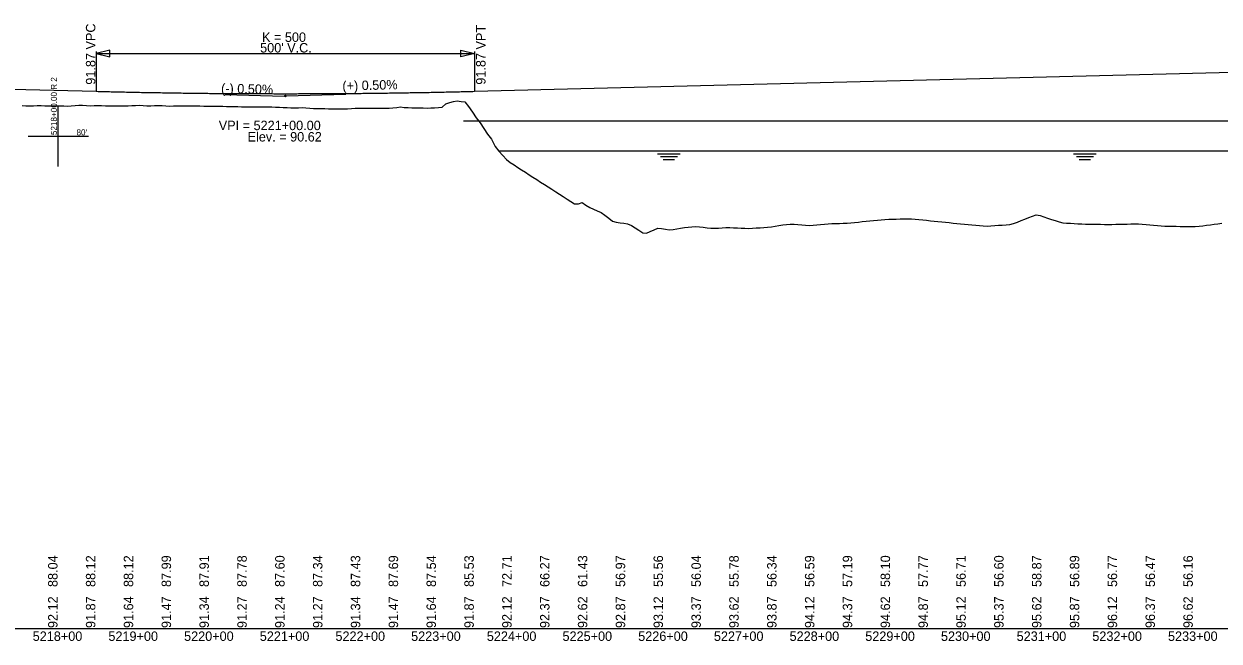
# Model space of a CAD drawing. Extents: x 2147288 to 2220488, y 740833 to 759333.
# Drawn here: x 2154136 to 2155715, y 750067 to 750882 of the extents above; entities that cross this region are included whole.
import ezdxf

# ---------------------------------------------------------------- set-up
doc = ezdxf.new("R2010")
doc.units = 0
for name, color, linetype in [('RD_DDB_GradeTX', 7, 'Continuous'), ('RD_DDB_Profile_Elev', 7, 'Continuous'), ('RD_DDB_Profile_EX', 7, 'Continuous'), ('RD_DDB_Profile_Lbl', 7, 'Continuous'), ('RD_DDB_Profile_PR', 7, 'Continuous'), ('RD_DDB_StaTX', 7, 'Continuous'), ('RD_DDB_StripGrade', 7, 'Continuous'), ('RD_DDB_VCLbl', 7, 'Continuous'), ('RD_GPK_Profile_Cell', 7, 'Continuous')]:
    doc.layers.add(name, color=color, linetype=linetype)

msp = doc.modelspace()

# ---------------------------------------------------------------- linework, layer by layer
at = {"layer": 'RD_DDB_GradeTX'}
for p, q in [((2154401.1, 750788.5), (2154480.1, 750786.5)), ((2154561.1, 750788.5), (2154482.1, 750786.5))]:
    msp.add_line(p, q, dxfattribs=at)
msp.add_circle((2154481.1, 750786.5), 1, dxfattribs=at)
at = {"layer": 'RD_DDB_Profile_Elev'}
for p, q in [((2154716.7, 750754), (2158451.2, 750754)), ((2154763.1, 750714), (2159128.1, 750714)), ((2154972.8, 750710.3), (2155002.8, 750710.3)), ((2154976.6, 750706.5), (2154999.1, 750706.5)), ((2155522.4, 750710.3), (2155552.4, 750710.3)), ((2155526.2, 750706.5), (2155548.7, 750706.5)), ((2154980.3, 750702.8), (2154995.3, 750702.8)), ((2155529.9, 750702.8), (2155544.9, 750702.8))]:
    msp.add_line(p, q, dxfattribs=at)
at = {"layer": 'RD_DDB_Profile_EX'}
for points in [[(2154133.3, 750773.9), (2154138.3, 750773.7), (2154143.3, 750773.6), (2154148.3, 750773.7), (2154153.3, 750774), (2154158.3, 750773.9), (2154163.3, 750773.7), (2154168.3, 750773.4), (2154173.3, 750773.4), (2154178.3, 750773.6), (2154183.3, 750773.7), (2154188.3, 750773.7), (2154193.3, 750773.3), (2154198.3, 750773.6), (2154203.3, 750774.1), (2154208.3, 750774.4), (2154213.3, 750774.6), (2154218.3, 750774), (2154223.3, 750773.5), (2154228.3, 750773.9), (2154233.3, 750774.1), (2154238.3, 750773.9), (2154243.3, 750773.8), (2154248.3, 750773.8), (2154253.3, 750773.7), (2154258.3, 750773.7), (2154263.3, 750773.7), (2154268.3, 750773.8), (2154273.3, 750773.8), (2154278.3, 750774), (2154283.3, 750774.1), (2154288.3, 750774.3), (2154293.3, 750774.2), (2154298.3, 750773.7), (2154303.3, 750773.7), (2154308.3, 750773.9), (2154313.3, 750774), (2154318.3, 750774), (2154323.3, 750773.5), (2154328.3, 750773.2), (2154333.3, 750773.6), (2154338.3, 750773.7), (2154343.3, 750773.5), (2154348.3, 750773.4), (2154353.3, 750773.5), (2154358.3, 750773.5), (2154363.3, 750773.5), (2154368.3, 750773.5), (2154373.3, 750773.2), (2154378.3, 750773), (2154383.3, 750773), (2154388.3, 750773), (2154393.3, 750773.1), (2154398.3, 750773), (2154403.3, 750772.9), (2154408.3, 750772.9), (2154413.3, 750772.9), (2154418.3, 750772.8), (2154423.3, 750772.5), (2154428.3, 750772.3), (2154433.3, 750772.3), (2154438.3, 750772.2), (2154443.3, 750772.4), (2154448.3, 750772.5), (2154453.3, 750772.5), (2154458.3, 750772.4), (2154463.3, 750772.2), (2154468.3, 750772), (2154473.3, 750771.7), (2154478.3, 750771.5), (2154483.3, 750771.3), (2154488.3, 750771.1), (2154493.3, 750770.9), (2154498.3, 750771.1), (2154503.3, 750771.3), (2154508.3, 750770.9), (2154513.3, 750770.5), (2154518.3, 750770.2), (2154523.3, 750770.1), (2154528.3, 750770.3), (2154533.3, 750770), (2154538.3, 750769.8)], [(2154538.3, 750769.8), (2154543.3, 750769.8), (2154548.3, 750769.7), (2154553.3, 750769.8), (2154558.3, 750769.7), (2154563.3, 750769.6), (2154568.3, 750770.1), (2154573.3, 750770.5), (2154578.3, 750770.5), (2154583.3, 750770.6), (2154588.3, 750770.6), (2154593.3, 750770.6), (2154598.3, 750770.5), (2154603.3, 750770.4), (2154608.3, 750770.4), (2154613.3, 750770.5), (2154618.3, 750770.7), (2154623.3, 750770.9), (2154628.3, 750771.6), (2154633.3, 750772.1), (2154638.3, 750771.3), (2154643.3, 750771.2), (2154648.3, 750771.1), (2154653.3, 750770.8), (2154658.3, 750771), (2154663.3, 750770.8), (2154668.3, 750770.6), (2154673.3, 750770.8), (2154678.3, 750770.8), (2154683.3, 750771.4), (2154688.3, 750772), (2154693.3, 750776.1), (2154698.3, 750777.8), (2154703.3, 750779.5), (2154708.3, 750780.2), (2154713.3, 750779.5), (2154718.3, 750778.7), (2154723.3, 750772.6), (2154728.3, 750765.1), (2154733.3, 750757.9), (2154738.3, 750751.2), (2154743.3, 750743.8), (2154748.3, 750736.1), (2154753.3, 750729.5), (2154758.3, 750720.1), (2154763.3, 750713.8), (2154768.3, 750708.2), (2154773.3, 750702.8), (2154778.3, 750698.8), (2154783.3, 750695.5), (2154788.3, 750692.3), (2154793.3, 750689.1), (2154798.3, 750685.9), (2154803.3, 750682.7), (2154808.3, 750679.5), (2154813.3, 750676.2), (2154818.3, 750673), (2154823.3, 750669.8), (2154828.3, 750666.6), (2154833.3, 750663.4), (2154838.3, 750660.2), (2154843.3, 750657), (2154848.3, 750653.7), (2154853.3, 750650.5), (2154858.3, 750647.3), (2154863.3, 750644.4), (2154868.3, 750644.1), (2154873.3, 750645.8), (2154878.3, 750642.4), (2154883.3, 750639.2), (2154888.3, 750637.1), (2154893.3, 750635), (2154898.3, 750632.9), (2154903.3, 750629.1), (2154908.3, 750625.2), (2154913.3, 750621.3), (2154918.3, 750620), (2154923.3, 750619.3), (2154928.3, 750618.6), (2154933.3, 750618), (2154938.3, 750615.8), (2154943.3, 750612.6), (2154948.3, 750609.3), (2154953.3, 750606.1), (2154958.3, 750605.3), (2154963.3, 750607.5), (2154968.3, 750609.7), (2154973.3, 750612), (2154978.3, 750611.7), (2154983.3, 750610.9), (2154988.3, 750610.1), (2154993.3, 750610.4), (2154998.3, 750611.3), (2155003.3, 750612.1), (2155008.3, 750612.9), (2155013.3, 750613.4), (2155018.3, 750614), (2155023.3, 750614.5), (2155028.3, 750614), (2155033.3, 750613.3), (2155038.3, 750612.6)], [(2155038.3, 750612.6), (2155043.3, 750611.9), (2155048.3, 750612), (2155053.3, 750612.3), (2155058.3, 750612.5), (2155063.3, 750612.8), (2155068.3, 750613), (2155073.3, 750612.7), (2155078.3, 750612.4), (2155083.3, 750612.2), (2155088.3, 750612), (2155093.3, 750611.8), (2155098.3, 750612), (2155103.3, 750612.4), (2155108.3, 750612.7), (2155113.3, 750613.1), (2155118.3, 750613.5), (2155123.3, 750613.9), (2155128.3, 750614.7), (2155133.3, 750615.5), (2155138.3, 750616.3), (2155143.3, 750617.1), (2155148.3, 750617.6), (2155153.3, 750617.2), (2155158.3, 750616.8), (2155163.3, 750616.4), (2155168.3, 750616), (2155173.3, 750615.6), (2155178.3, 750616.1), (2155183.3, 750616.6), (2155188.3, 750617), (2155193.3, 750617.5), (2155198.3, 750618), (2155203.3, 750618.4), (2155208.3, 750618.1), (2155213.3, 750618.4), (2155218.3, 750618.6), (2155223.3, 750618.9), (2155228.3, 750619.2), (2155233.3, 750619.5), (2155238.3, 750620.2), (2155243.3, 750620.7), (2155248.3, 750621.2), (2155253.3, 750621.7), (2155258.3, 750622.2), (2155263.3, 750622.6), (2155268.3, 750623.1), (2155273.3, 750623.7), (2155278.3, 750623.9), (2155283.3, 750624), (2155288.3, 750624.2), (2155293.3, 750624.3), (2155298.3, 750624.4), (2155303.3, 750624.6), (2155308.3, 750624.6), (2155313.3, 750624.1), (2155318.3, 750623.6), (2155323.3, 750623.1), (2155328.3, 750622.6), (2155333.3, 750622), (2155338.3, 750621.5), (2155343.3, 750620.9), (2155348.3, 750620.4), (2155353.3, 750619.9), (2155358.3, 750619.4), (2155363.3, 750618.9), (2155368.3, 750618.4), (2155373.3, 750617.7), (2155378.3, 750617.2), (2155383.3, 750616.8), (2155388.3, 750616.4), (2155393.3, 750616), (2155398.3, 750615.6), (2155403.3, 750615.2), (2155408.3, 750614.8), (2155413.3, 750615.2), (2155418.3, 750615.5), (2155423.3, 750615.9), (2155428.3, 750616.2), (2155433.3, 750616.6), (2155438.3, 750616.9), (2155443.3, 750618.3), (2155448.3, 750620.2), (2155453.3, 750622.2), (2155458.3, 750624.1), (2155463.3, 750626.1), (2155468.3, 750628), (2155473.3, 750629.8), (2155478.3, 750628.7), (2155483.3, 750627), (2155488.3, 750625.4), (2155493.3, 750623.7), (2155498.3, 750622.1), (2155503.3, 750620.4), (2155508.3, 750619.2), (2155513.3, 750618.8), (2155518.3, 750618.5), (2155523.3, 750618.3), (2155528.3, 750618), (2155533.3, 750617.7), (2155538.3, 750617.5)], [(2155538.3, 750617.5), (2155543.3, 750617.3), (2155548.3, 750617.3), (2155553.3, 750617.3), (2155558.3, 750617.2), (2155563.3, 750617.1), (2155568.3, 750617), (2155573.3, 750617), (2155578.3, 750617.2), (2155583.3, 750617.3), (2155588.3, 750617.5), (2155593.3, 750617.6), (2155598.3, 750617.7), (2155603.3, 750617.9), (2155608.3, 750618), (2155613.3, 750617.4), (2155618.3, 750617), (2155623.3, 750616.5), (2155628.3, 750616), (2155633.3, 750615.6), (2155638.3, 750615.1), (2155643.3, 750614.7), (2155648.3, 750614.7), (2155653.3, 750614.6), (2155658.3, 750614.6), (2155663.3, 750614.5), (2155668.3, 750614.4), (2155673.3, 750614.3), (2155678.3, 750614.2), (2155683.3, 750614.3), (2155688.3, 750614.8), (2155693.3, 750615.4), (2155698.3, 750616), (2155703.3, 750616.6), (2155708.3, 750617.2), (2155713.3, 750617.7), (2155718.3, 750618.5)]]:
    msp.add_lwpolyline(points, dxfattribs=at)
at = {"layer": 'RD_DDB_Profile_PR'}
for p, q in [((2154731.1, 750792.8), (2156331.1, 750832.8)), ((2154031.1, 750797.8), (2154231.1, 750792.8))]:
    msp.add_line(p, q, dxfattribs=at)
msp.add_spline([(2154231.1, 750792.8), (2154241.1, 750792.5), (2154251.1, 750792.3), (2154261.1, 750792.1), (2154271.1, 750791.8), (2154281.1, 750791.6), (2154291.1, 750791.4), (2154301.1, 750791.3), (2154311.1, 750791.1), (2154321.1, 750790.9), (2154331.1, 750790.8), (2154341.1, 750790.6), (2154351.1, 750790.5), (2154361.1, 750790.4), (2154371.1, 750790.2), (2154381.1, 750790.1), (2154391.1, 750790), (2154401.1, 750790), (2154411.1, 750789.9), (2154421.1, 750789.8), (2154431.1, 750789.8), (2154441.1, 750789.7), (2154451.1, 750789.7), (2154461.1, 750789.7), (2154471.1, 750789.6), (2154481.1, 750789.6), (2154491.1, 750789.6), (2154501.1, 750789.7), (2154511.1, 750789.7), (2154521.1, 750789.7), (2154531.1, 750789.8), (2154541.1, 750789.8), (2154551.1, 750789.9), (2154561.1, 750790), (2154571.1, 750790), (2154581.1, 750790.1), (2154591.1, 750790.2), (2154601.1, 750790.4), (2154611.1, 750790.5), (2154621.1, 750790.6), (2154631.1, 750790.8), (2154641.1, 750790.9), (2154651.1, 750791.1), (2154661.1, 750791.3), (2154671.1, 750791.4), (2154681.1, 750791.6), (2154691.1, 750791.8), (2154701.1, 750792.1), (2154711.1, 750792.3), (2154721.1, 750792.5), (2154731.1, 750792.8)], degree=3, dxfattribs=at)
at = {"layer": 'RD_DDB_VCLbl'}
for p, q in [((2154231.1, 750845.3), (2154231.1, 750792.8)), ((2154231.1, 750842.8), (2154731.1, 750842.8)), ((2154731.1, 750845.3), (2154731.1, 750792.8))]:
    msp.add_line(p, q, dxfattribs=at)
for points in [[(2154249.1, 750847.3), (2154231.1, 750842.8), (2154249.1, 750838.3)], [(2154713.1, 750847.3), (2154731.1, 750842.8), (2154713.1, 750838.3)]]:
    msp.add_lwpolyline(points, close=True, dxfattribs=at)
at = {"layer": 'RD_GPK_Profile_Cell'}
for p, q in [((2154181.1, 750693.4), (2154181.1, 750773.4)), ((2154141.1, 750733.4), (2154221.1, 750733.4)), ((2148888.3, 750083.4), (2170488.3, 750083.4))]:
    msp.add_line(p, q, dxfattribs=at)

# ---------------------------------------------------------------- texts
at = {"layer": 'RD_DDB_GradeTX'}
for s, rotation, p in [('(-) 0.50%', 358.5679, (2154396.1, 750790.6)), ('(+) 0.50%', 1.4321, (2154556.6, 750793.7))]:
    msp.add_text(s, height=12.5, rotation=rotation, dxfattribs=at).set_placement(p)
at = {"layer": 'RD_DDB_Profile_Lbl'}
for s, p in [('VPI = 5221+00.00', (2154393.1, 750741.5)), ('Elev. = 90.62', (2154431.2, 750726.5))]:
    msp.add_text(s, height=12.5, dxfattribs=at).set_placement(p)
at = {"layer": 'RD_DDB_StaTX'}
for s, p in [('5218+00', (2154147.3, 750067.2)), ('5219+00', (2154247.3, 750067.2)), ('5220+00', (2154347.3, 750067.2)), ('5221+00', (2154447.3, 750067.2)), ('5222+00', (2154547.3, 750067.2)), ('5223+00', (2154647.3, 750067.2)), ('5224+00', (2154747.3, 750067.2)), ('5225+00', (2154847.3, 750067.2)), ('5226+00', (2154947.3, 750067.2)), ('5227+00', (2155047.3, 750067.2)), ('5228+00', (2155147.3, 750067.2)), ('5229+00', (2155247.3, 750067.2)), ('5230+00', (2155347.3, 750067.2)), ('5231+00', (2155447.3, 750067.2)), ('5232+00', (2155547.3, 750067.2)), ('5233+00', (2155647.3, 750067.2))]:
    msp.add_text(s, height=12.5, dxfattribs=at).set_placement(p)
at = {"layer": 'RD_DDB_StripGrade'}
for s, p in [('91.87 VPC', (2154230.1, 750801.5)), ('91.87 VPT', (2154745.6, 750801.5)), ('88.04', (2154180.1, 750138.4)), ('88.12', (2154230.1, 750138.4)), ('88.12', (2154280.1, 750138.4)), ('87.99', (2154330.1, 750138.4)), ('87.91', (2154380.1, 750138.4)), ('87.78', (2154430.1, 750138.4)), ('87.60', (2154480.1, 750138.4)), ('87.34', (2154530.1, 750138.4)), ('87.43', (2154580.1, 750138.4)), ('87.69', (2154630.1, 750138.4)), ('87.54', (2154680.1, 750138.4)), ('85.53', (2154730.1, 750138.4)), ('72.71', (2154780.1, 750138.4)), ('66.27', (2154830.1, 750138.4)), ('61.43', (2154880.1, 750138.4)), ('56.97', (2154930.1, 750138.4)), ('55.56', (2154980.1, 750138.4)), ('56.04', (2155030.1, 750138.4)), ('55.78', (2155080.1, 750138.4)), ('56.34', (2155130.1, 750138.4)), ('56.59', (2155180.1, 750138.4)), ('57.19', (2155230.1, 750138.4)), ('58.10', (2155280.1, 750138.4)), ('57.77', (2155330.1, 750138.4)), ('56.71', (2155380.1, 750138.4)), ('56.60', (2155430.1, 750138.4)), ('58.87', (2155480.1, 750138.4)), ('56.89', (2155530.1, 750138.4)), ('56.77', (2155580.1, 750138.4)), ('56.47', (2155630.1, 750138.4)), ('56.16', (2155680.1, 750138.4)), ('92.12', (2154180.1, 750084.2)), ('91.87', (2154230.1, 750084.2)), ('91.64', (2154280.1, 750084.2)), ('91.47', (2154330.1, 750084.2)), ('91.34', (2154380.1, 750084.2)), ('91.27', (2154430.1, 750084.2)), ('91.24', (2154480.1, 750084.2)), ('91.27', (2154530.1, 750084.2)), ('91.34', (2154580.1, 750084.2)), ('91.47', (2154630.1, 750084.2)), ('91.64', (2154680.1, 750084.2)), ('91.87', (2154730.1, 750084.2)), ('92.12', (2154780.1, 750084.2)), ('92.37', (2154830.1, 750084.2)), ('92.62', (2154880.1, 750084.2)), ('92.87', (2154930.1, 750084.2)), ('93.12', (2154980.1, 750084.2)), ('93.37', (2155030.1, 750084.2)), ('93.62', (2155080.1, 750084.2)), ('93.87', (2155130.1, 750084.2)), ('94.12', (2155180.1, 750084.2)), ('94.37', (2155230.1, 750084.2)), ('94.62', (2155280.1, 750084.2)), ('94.87', (2155330.1, 750084.2)), ('95.12', (2155380.1, 750084.2)), ('95.37', (2155430.1, 750084.2)), ('95.62', (2155480.1, 750084.2)), ('95.87', (2155530.1, 750084.2)), ('96.12', (2155580.1, 750084.2)), ('96.37', (2155630.1, 750084.2)), ('96.62', (2155680.1, 750084.2))]:
    msp.add_text(s, height=12.5, rotation=90, dxfattribs=at).set_placement(p)
at = {"layer": 'RD_DDB_VCLbl'}
for s, p in [('K = 500', (2154450.3, 750858)), ("500' V.C.", (2154447.8, 750844))]:
    msp.add_text(s, height=12.5, dxfattribs=at).set_placement(p)
at = {"layer": 'RD_GPK_Profile_Cell'}
msp.add_text('5218+00.00 R 2', height=8, rotation=90, dxfattribs=at).set_placement((2154179.3, 750735))
msp.add_text("80'", height=8, dxfattribs=at).set_placement((2154205.2, 750734.6))

doc.saveas('drawing.dxf')
